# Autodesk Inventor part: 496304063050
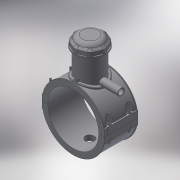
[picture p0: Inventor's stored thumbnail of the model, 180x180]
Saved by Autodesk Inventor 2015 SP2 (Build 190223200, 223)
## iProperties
Created: 2017-07
Part Number: 496304063050
Material: Generic
Description: PLASSON TAPPING SADDLE 63x50
Document SubType Name: Modeling
Designer: KIM
Mass: 486.155 g
Surface Area: 1470.56 cm^2
Volume: 486.155 cm^3
Density: 1 g/cm^3
Appearance: Default
Author: KIM
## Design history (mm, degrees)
derived "496304.ipt"
feature "Solid1::496304.ipt"
feature "Solid2::496304.ipt"
feature "Solid4::496304.ipt"
feature "Solid5::496304.ipt"
tag "TaggingFeature1"
body "Solid1"
body "Solid2"
other parameters: "d0" = 63, "d3" = 15.75, "d4" = 118, "d5" = 0, "d6" = 0.1, "d8" = 0, "d19" = 6, "d20" = 6, "d21" = 70.8, "d23" = 0, "d24" = 35.4, "d26" = 0, "d29" = 3, "d30" = 21, "d31" = 6, "d32" = 0, "d33" = 0, "d34" = 0.6, "d40" = 42.588, "d41" = 63, "d43" = 0, "d45" = 0, "d47" = 111.75, "d70" = 15, "d72" = 0, "d73" = 6, "d75" = 5, "d76" = 0, "d77" = 3.15, "d78" = 61.5, "d79" = 15, "d80" = 47.2, "d82" = 5 deg, "d84" = 4, "d85" = 14, "d86" = 0, "d87" = 3, "d88" = 0, "d89" = 1, "d90" = 1, "d91" = 94.4, "d92" = 0, "d93" = 0.5, "d94" = 33.15789, "d96" = 83.538, "d97" = 2.36, "d98" = 0, "d102" = 0.63, "d120" = 140 deg, "d121" = 24.228, "d122" = 20 deg, "d123" = 163.8, "d124" = 49.14, "d126" = 0, "d143" = 64.89, "d145" = 14.53846, "d149" = 0.945, "d150" = 15.99231, "d153" = 118, "d154" = 0, "d156" = 40.95, "d157" = 160 deg, "d159" = 3.78, "d161" = 0.945, "d162" = 70.8, "d163" = 0, "d164" = 31.5, "d167" = 6.3, "d168" = 39.95122, "d170" = 3.375, "d172" = 0, "d173" = 1, "d175" = 31.5, "d176" = 20 deg, "d177" = 4.41, "d178" = 18.9, "d180" = 0, "d183" = 7.56, "d184" = 3.528, "d185" = 38.35, "d186" = 38.35, "d187" = 40.95, "d188" = 5.67, "d189" = 4.41, "d190" = 0, "d191" = 61.425, "d193" = 6.3, "d194" = 4.13, "d195" = 90 deg, "d197" = 0, "d199" = 0, "d200" = 9.45, "d202" = 0, "d203" = 177, "d204" = 59.85, "d205" = 44.1, "d206" = 53.55, "d207" = 132.75, "d208" = 138.06, "d209" = 164.61, "d210" = 54.18, "d211" = 63, "d212" = 50.4, "d213" = 35.1, "d216" = 0, "d217" = 6.3, "d218" = 6.3, "d219" = 1.26, "d222" = 63, "d224" = 0, "d230" = 3.78, "d233" = 6, "d237" = 35.4, "d238" = 6.02433, "d240" = 35.4, "d241" = 35.4, "d242" = 35.4, "d243" = 6, "d244" = 35.4, "d245" = 35.4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
